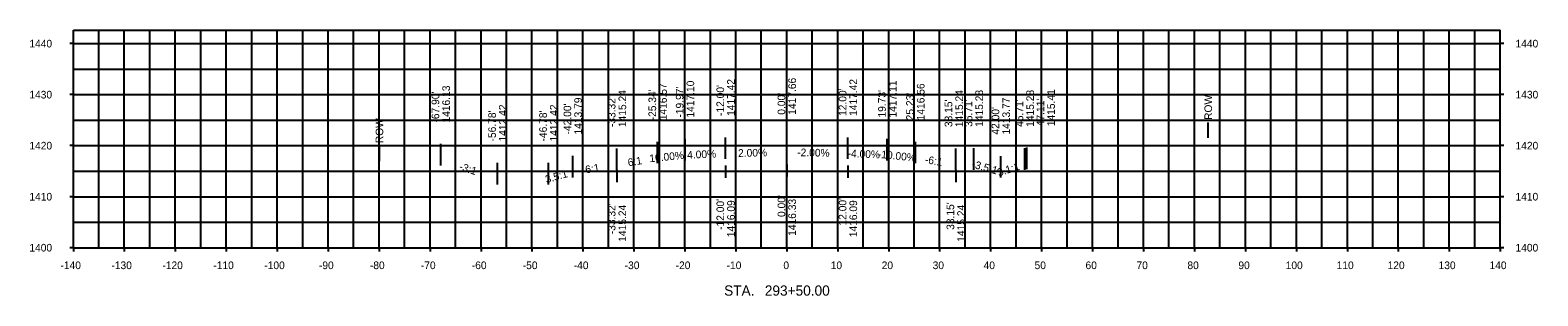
# Model space of a CAD drawing. Extents: x -148 to 147, y 1391 to 1443.
import ezdxf

# ---------------------------------------------------------------- set-up
doc = ezdxf.new("R2010")
doc.units = 0
for name, color, linetype in [('Default', 7, 'Continuous'), ('SheetBorder', 7, 'Continuous'), ('SheetGridMajor', 7, 'Continuous'), ('SheetGridMinor', 7, 'Continuous'), ('Text', 7, 'Continuous')]:
    doc.layers.add(name, color=color, linetype=linetype)

msp = doc.modelspace()

# ---------------------------------------------------------------- linework, layer by layer
at = {"layer": 'Default'}
for p, q in [((82.69, 1421.55), (82.69, 1424.55)), ((-79.94, 1416.98), (-79.94, 1419.98))]:
    msp.add_line(p, q, dxfattribs=at)
at = {"layer": 'SheetBorder'}
for p, q in [((-140, 1442.63), (140, 1442.63)), ((-140, 1400), (-140, 1442.63)), ((140, 1400), (140, 1442.63)), ((-140, 1400), (140, 1400))]:
    msp.add_line(p, q, dxfattribs=at)
at = {"layer": 'SheetGridMajor'}
for p, q in [((-130, 1400), (-130, 1442.63)), ((-120, 1400), (-120, 1442.63)), ((-110, 1400), (-110, 1442.63)), ((-100, 1400), (-100, 1442.63)), ((-90, 1400), (-90, 1442.63)), ((-80, 1400), (-80, 1442.63)), ((-70, 1400), (-70, 1442.63)), ((-60, 1400), (-60, 1442.63)), ((-50, 1400), (-50, 1442.63)), ((-40, 1400), (-40, 1442.63)), ((-30, 1400), (-30, 1442.63)), ((-20, 1400), (-20, 1442.63)), ((-10, 1400), (-10, 1442.63)), ((0, 1400), (0, 1442.63)), ((10, 1400), (10, 1442.63)), ((20, 1400), (20, 1442.63)), ((30, 1400), (30, 1442.63)), ((40, 1400), (40, 1442.63)), ((50, 1400), (50, 1442.63)), ((60, 1400), (60, 1442.63)), ((70, 1400), (70, 1442.63)), ((80, 1400), (80, 1442.63)), ((90, 1400), (90, 1442.63)), ((100, 1400), (100, 1442.63)), ((110, 1400), (110, 1442.63)), ((120, 1400), (120, 1442.63)), ((130, 1400), (130, 1442.63)), ((-140, 1440), (-140.72, 1440)), ((-140, 1440), (140, 1440)), ((140.72, 1440), (140, 1440)), ((-140, 1430), (-140.72, 1430)), ((-140, 1430), (140, 1430)), ((140.72, 1430), (140, 1430)), ((-140, 1420), (-140.72, 1420)), ((-140, 1420), (140, 1420)), ((140.72, 1420), (140, 1420)), ((-140, 1410), (-140.72, 1410)), ((-140, 1410), (140, 1410)), ((140.72, 1410), (140, 1410)), ((-140, 1400), (-140.72, 1400)), ((-140, 1400), (-140, 1399.28)), ((-130, 1400), (-130, 1399.28)), ((-120, 1400), (-120, 1399.28)), ((-110, 1400), (-110, 1399.28)), ((-100, 1400), (-100, 1399.28)), ((-90, 1400), (-90, 1399.28)), ((-80, 1400), (-80, 1399.28)), ((-70, 1400), (-70, 1399.28)), ((-60, 1400), (-60, 1399.28)), ((-50, 1400), (-50, 1399.28)), ((-40, 1400), (-40, 1399.28)), ((-30, 1400), (-30, 1399.28)), ((-20, 1400), (-20, 1399.28)), ((-10, 1400), (-10, 1399.28)), ((0, 1400), (0, 1399.28)), ((10, 1400), (10, 1399.28)), ((20, 1400), (20, 1399.28)), ((30, 1400), (30, 1399.28)), ((40, 1400), (40, 1399.28)), ((50, 1400), (50, 1399.28)), ((60, 1400), (60, 1399.28)), ((70, 1400), (70, 1399.28)), ((80, 1400), (80, 1399.28)), ((90, 1400), (90, 1399.28)), ((100, 1400), (100, 1399.28)), ((110, 1400), (110, 1399.28)), ((120, 1400), (120, 1399.28)), ((130, 1400), (130, 1399.28)), ((140, 1400), (140, 1399.28)), ((140.72, 1400), (140, 1400))]:
    msp.add_line(p, q, dxfattribs=at)
at = {"layer": 'SheetGridMinor'}
for p, q in [((-135, 1400), (-135, 1442.63)), ((-125, 1400), (-125, 1442.63)), ((-115, 1400), (-115, 1442.63)), ((-105, 1400), (-105, 1442.63)), ((-95, 1400), (-95, 1442.63)), ((-85, 1400), (-85, 1442.63)), ((-75, 1400), (-75, 1442.63)), ((-65, 1400), (-65, 1442.63)), ((-55, 1400), (-55, 1442.63)), ((-45, 1400), (-45, 1442.63)), ((-35, 1400), (-35, 1442.63)), ((-25, 1400), (-25, 1442.63)), ((-15, 1400), (-15, 1442.63)), ((-5, 1400), (-5, 1442.63)), ((5, 1400), (5, 1442.63)), ((15, 1400), (15, 1442.63)), ((25, 1400), (25, 1442.63)), ((35, 1400), (35, 1442.63)), ((45, 1400), (45, 1442.63)), ((55, 1400), (55, 1442.63)), ((65, 1400), (65, 1442.63)), ((75, 1400), (75, 1442.63)), ((85, 1400), (85, 1442.63)), ((95, 1400), (95, 1442.63)), ((105, 1400), (105, 1442.63)), ((115, 1400), (115, 1442.63)), ((125, 1400), (125, 1442.63)), ((135, 1400), (135, 1442.63)), ((-140, 1435), (140, 1435)), ((-140, 1425), (140, 1425)), ((-140, 1415), (140, 1415)), ((-140, 1405), (140, 1405))]:
    msp.add_line(p, q, dxfattribs=at)
at = {"layer": 'Text'}
for p, q in [((-67.9, 1416.13), (-67.9, 1420.33)), ((-25.34, 1416.57), (-25.34, 1420.77)), ((-19.97, 1417.1), (-19.97, 1421.3)), ((-12, 1417.42), (-12, 1421.62)), ((-12, 1417.42), (-12, 1421.62)), ((0, 1417.66), (0, 1421.86)), ((0, 1417.66), (0, 1421.86)), ((0, 1417.66), (0, 1421.86)), ((0, 1417.66), (0, 1421.86)), ((12, 1417.42), (12, 1421.62)), ((12, 1417.42), (12, 1421.62)), ((19.73, 1417.11), (19.73, 1421.31)), ((25.23, 1416.56), (25.23, 1420.76)), ((-42, 1413.79), (-42, 1417.99)), ((-33.32, 1415.24), (-33.32, 1419.44)), ((33.15, 1415.24), (33.15, 1419.44)), ((33.15, 1415.24), (33.15, 1419.44)), ((36.71, 1415.28), (36.71, 1419.48)), ((42, 1413.77), (42, 1417.97)), ((46.71, 1415.28), (46.71, 1419.48)), ((47.11, 1415.41), (47.11, 1419.61)), ((-56.78, 1412.42), (-56.78, 1416.62)), ((-46.78, 1412.42), (-46.78, 1416.62)), ((-33.32, 1415.24), (-33.32, 1412.84)), ((-12, 1416.09), (-12, 1413.69)), ((0, 1416.33), (0, 1413.93)), ((0, 1416.33), (0, 1413.93)), ((0, 1416.33), (0, 1413.93)), ((12, 1416.09), (12, 1413.69)), ((33.15, 1415.24), (33.15, 1412.84))]:
    msp.add_line(p, q, dxfattribs=at)

# ---------------------------------------------------------------- texts
at = {"layer": 'Default'}
for s, height, p in [('1440', 1.5, (-148.63, 1439.25)), ('1440', 1.5, (143, 1439.25)), ('1430', 1.5, (-148.63, 1429.25)), ('1430', 1.5, (143, 1429.25)), ('1420', 1.5, (-148.63, 1419.25)), ('1420', 1.5, (143, 1419.25)), ('1410', 1.5, (-148.63, 1409.25)), ('1410', 1.5, (143, 1409.25)), ('1400', 1.5, (-148.63, 1399.25)), ('1400', 1.5, (143, 1399.25)), ('-140', 1.5, (-142.53, 1395.8)), ('-130', 1.5, (-132.53, 1395.8)), ('-120', 1.5, (-122.53, 1395.8)), ('-110', 1.5, (-112.53, 1395.8)), ('-100', 1.5, (-102.53, 1395.8)), ('-90', 1.5, (-91.81, 1395.8)), ('-80', 1.5, (-81.81, 1395.8)), ('-70', 1.5, (-71.81, 1395.8)), ('-60', 1.5, (-61.81, 1395.8)), ('-50', 1.5, (-51.81, 1395.8)), ('-40', 1.5, (-41.81, 1395.8)), ('-30', 1.5, (-31.81, 1395.8)), ('-20', 1.5, (-21.81, 1395.8)), ('-10', 1.5, (-11.81, 1395.8)), ('0', 1.5, (-0.67, 1395.8)), ('10', 1.5, (8.62, 1395.8)), ('20', 1.5, (18.62, 1395.8)), ('30', 1.5, (28.62, 1395.8)), ('40', 1.5, (38.62, 1395.8)), ('50', 1.5, (48.62, 1395.8)), ('60', 1.5, (58.62, 1395.8)), ('70', 1.5, (68.62, 1395.8)), ('80', 1.5, (78.62, 1395.8)), ('90', 1.5, (88.62, 1395.8)), ('100', 1.5, (97.9, 1395.8)), ('110', 1.5, (107.9, 1395.8)), ('120', 1.5, (117.9, 1395.8)), ('130', 1.5, (127.9, 1395.8)), ('140', 1.5, (137.9, 1395.8)), ('STA.', 2.004, (-12.3, 1390.6)), ('293+50.00', 2.004, (-4.31, 1390.6))]:
    msp.add_text(s, height=height, dxfattribs=at).set_placement(p)
for p in [(83.45, 1425.04), (-79.18, 1420.48)]:
    msp.add_text('ROW', height=1.5, rotation=90, dxfattribs=at).set_placement(p)
at = {"layer": 'Text'}
for s, rotation, p in [('1416.57', 90, (-23.54, 1424.97)), ('1417.10', 90, (-18.17, 1425.5)), ('1417.42', 90, (-10.2, 1425.82)), ('1417.42', 90, (-10.2, 1425.82)), ('1417.66', 90, (1.8, 1426.06)), ('1417.66', 90, (1.8, 1426.06)), ('1417.66', 90, (1.8, 1426.06)), ('1417.66', 90, (1.8, 1426.06)), ('1417.42', 90, (13.8, 1425.82)), ('1417.42', 90, (13.8, 1425.82)), ('1417.11', 90, (21.53, 1425.51)), ('1416.56', 90, (27.03, 1424.96)), ("-67.90'", 90, (-68.2, 1424.53)), ('1416.13', 90, (-66.1, 1424.53)), ('1413.79', 90, (-40.2, 1422.19)), ("-33.32'", 90, (-33.62, 1423.64)), ('1415.24', 90, (-31.52, 1423.64)), ("-25.34'", 90, (-25.64, 1424.97)), ("-19.97'", 90, (-20.27, 1425.5)), ("-12.00'", 90, (-12.3, 1425.82)), ("-12.00'", 90, (-12.3, 1425.82)), ("0.00'", 90, (-0.3, 1426.06)), ("0.00'", 90, (-0.3, 1426.06)), ("0.00'", 90, (-0.3, 1426.06)), ("0.00'", 90, (-0.3, 1426.06)), ("12.00'", 90, (11.7, 1425.82)), ("12.00'", 90, (11.7, 1425.82)), ("19.73'", 90, (19.43, 1425.51)), ("25.23'", 90, (24.93, 1424.96)), ('1415.24', 90, (34.58, 1423.64)), ('1415.24', 90, (34.58, 1423.64)), ('1415.28', 90, (38.51, 1423.68)), ('1413.77', 90, (43.8, 1422.17)), ('1415.28', 90, (48.51, 1423.68)), ("47.11'", 90, (50.51, 1423.81)), ('1415.41', 90, (52.61, 1423.81)), ("-56.78'", 90, (-57.08, 1420.82)), ('1412.42', 90, (-54.98, 1420.82)), ("-46.78'", 90, (-47.08, 1420.82)), ('1412.42', 90, (-44.98, 1420.82)), ("-42.00'", 90, (-42.3, 1422.19)), ("33.15'", 90, (32.48, 1423.64)), ("33.15'", 90, (32.48, 1423.64)), ("36.71'", 90, (36.41, 1423.68)), ("42.00'", 90, (41.7, 1422.17)), ("46.71'", 90, (46.41, 1423.68)), ('6:1', 9.4642, (-31.08, 1415.94)), ('10.00%', 5.7106, (-26.89, 1416.74)), ('4.00%', 2.2906, (-19.52, 1417.45)), ('2.00%', 1.1458, (-9.54, 1417.8)), ('-2.00%', 358.8542, (2.04, 1417.95)), ('-4.00%', 357.7094, (11.91, 1417.76)), ('-10.00%', 354.2894, (17.82, 1417.63)), ('-6:1', 350.5358, (27.02, 1416.59)), ('-3:1', 341.5668, (-64.42, 1415.3)), ('3.5:1', 15.9446, (-47.17, 1412.64)), ('6:1', 9.4642, (-39.41, 1414.55)), ('-3.5:1', 344.0554, (36.18, 1415.76)), ('3.1:1', 17.7904, (41.6, 1413.97)), ("-33.32'", 90, (-33.62, 1402.64)), ('1415.24', 90, (-31.52, 1401.16)), ("-12.00'", 90, (-12.3, 1403.49)), ('1416.09', 90, (-10.2, 1402.05)), ("0.00'", 90, (-0.3, 1406.02)), ("0.00'", 90, (-0.3, 1406.02)), ("0.00'", 90, (-0.3, 1406.02)), ('1416.33', 90, (1.8, 1402.32)), ('1416.33', 90, (1.8, 1402.32)), ('1416.33', 90, (1.8, 1402.32)), ("12.00'", 90, (11.7, 1404.35)), ('1416.09', 90, (13.8, 1402.05)), ("33.15'", 90, (32.85, 1403.5)), ('1415.24', 90, (34.95, 1401.16))]:
    msp.add_text(s, height=1.5, rotation=rotation, dxfattribs=at).set_placement(p)

doc.saveas('drawing.dxf')
